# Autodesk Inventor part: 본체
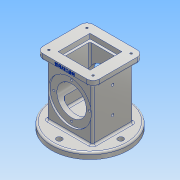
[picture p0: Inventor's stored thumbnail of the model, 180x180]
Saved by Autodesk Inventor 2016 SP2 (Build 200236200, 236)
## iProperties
Created: 2018-10
Part Number: 본체
Material: 알루미늄 6061
Document SubType Name: Modeling
Designer: Administrator
Mass: 984.858 g
Surface Area: 745.107 cm^2
Volume: 364.762 cm^3
Density: 2.7 g/cm^3
Appearance: 알루미늄 - 평지
Author: Administrator
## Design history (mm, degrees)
sketch "스케치1"
  geometry: C1 r 62.5 at (0, 0); 1 further point
  constraints: 1 centre point, 1 coincident
  dimensions: "d0" = 125 diameter of C1
extrude "돌출1" new body sketch "스케치1" distance "d1" = 10; taper "d2" = 0 deg
fillet "모깎기1" dims "d3" = 3
sketch "스케치2"
  geometry: C1 r 59.5 at (0, 0) reference; C2 r 4.5 at (0, 50); C3 r 4.5 at (-50, 0); C4 r 4.5 at (50, 0); C5 r 4.5 at (0, -50); A1 r 50 centre (0, 0) between (0, 50) and (-50, 0)
  constraints: 5 centre point, 4 point on circle, 1 coincident
  dimensions: "d4" = 100 diameter of A1; "d5" = 9 diameter of C3; "d6" = 9 diameter of C2; "d7" = 9 diameter of C5; "d8" = 9 diameter of C4
extrude "돌출2" cut sketch "스케치2" distance "d9" = 10; taper "d10" = 0 deg
sketch "스케치3"
  geometry: L1 (-37, -33)-(37, -33); L2 (37, -33)-(37, 33); L3 (37, 33)-(-37, 33); L4 (-37, 33)-(-37, -33); L5 (-37, -33)-(37, 33); L6 (37, -33)-(-37, 33); C1 r 59.5 at (0, 0) reference
  constraints: 12 end point, 2 midpoint, 2 parallel, 1 horizontal, 1 perpendicular
  dimensions: "d11" = 74 distance of L2.end L3.end; "d12" = 66 distance of L1.end L2.end
extrude "돌출3" join sketch "스케치3" distance "d13" = 88; taper "d14" = 0 deg
sketch "스케치4"
  geometry: L1 (-46, -41)-(46, -41); L2 (46, -41)-(46, 41); L3 (46, 41)-(-46, 41); L4 (-46, 41)-(-46, -41); L5 (-46, -41)-(46, 41); L6 (46, -41)-(-46, 41); 1 further point
  constraints: 12 end point, 2 midpoint, 2 parallel, 1 horizontal, 1 perpendicular
  dimensions: "d15" = 92 distance of L2.end L3.end; "d16" = 82 distance of L1.end L2.end
extrude "돌출4" join sketch "스케치4" distance "d17" = 10; taper "d18" = 0 deg
fillet "모깎기2" dims "d19" = 10
sketch "스케치5"
  geometry: A1 r 10 centre (-36, 31) between (-36, 41) and (-46, 31) reference; A2 r 10 centre (-36, -31) between (-46, -31) and (-36, -41) reference; A3 r 10 centre (36, -31) between (36, -41) and (46, -31) reference; A4 r 10 centre (36, 31) between (46, 31) and (36, 41) reference; 1 further point
hole "구멍1" sketch "스케치5" at (-36, 31), (36, 31), (36, -31), (-36, -31) diameter "d20" = 3.242; stored, may be unused: countersink angle "d24" = 90 deg, drill point angle "d26" = 118 deg; dims "d21" = 4, "d22" = 4, "d23" = 2, "d25" = 6
sketch "스케치6"
  geometry: L1 (37, -10)-(37, 44); C1 r 35 at (37, 44)
  constraints: 2 end point, 1 centre point, 1 coincident, 1 vertical
  dimensions: "d27" = 54 distance of L1.start L1.end; "d28" = 70 diameter of C1
extrude "돌출5" cut sketch "스케치6" distance "d29" = 3; taper "d30" = 0 deg
sketch "스케치7"
  geometry: C1 r 35 at (0, 0) reference; C2 r 24 at (0, 0); 1 further point
  constraints: 1 centre point, 1 coincident
  dimensions: "d31" = 48 diameter of C2
extrude "돌출6" cut sketch "스케치7" distance "d32" = 8; taper "d33" = 0 deg
sketch "스케치8" dims "d34" = 58
  geometry: C1 r 35 at (0, 0) reference; 3 further points
  constraints: 1 coincident, 1 vertical alignment, 2 other
hole "구멍2" sketch "스케치8" at (0, 29) diameter "d35" = 3.242; stored, may be unused: countersink angle "d39" = 90 deg, drill point angle "d41" = 118 deg; dims "d36" = 4, "d37" = 4, "d38" = 2, "d40" = 6
fillet "모깎기3" dims "d45" = 3
fillet "모깎기4" dims "d46" = 3
fillet "모깎기5" dims "d47" = 3
fillet "모깎기6" dims "d48" = 3
sketch "스케치9"
  geometry: L1 (-26, -26)-(26, -26); L2 (26, -26)-(26, 26); L3 (26, 26)-(-26, 26); L4 (-26, 26)-(-26, -26); L5 (-26, -26)-(26, 26); L6 (26, -26)-(-26, 26); 1 further point
  constraints: 12 end point, 2 midpoint, 2 parallel, 1 horizontal, 1 perpendicular
  dimensions: "d49" = 52 distance of L2.end L3.end; "d50" = 52 distance of L1.end L2.end
extrude "돌출7" cut sketch "스케치9" distance "d51" = 8; taper "d52" = 0 deg
sketch "스케치10"
  geometry: L1 (-22, -22)-(22, -22); L2 (22, -22)-(22, 22); L3 (22, 22)-(-22, 22); L4 (-22, 22)-(-22, -22); L5 (-22, -22)-(22, 22); L6 (22, -22)-(-22, 22); 1 further point
  constraints: 12 end point, 2 midpoint, 2 parallel, 1 horizontal, 1 perpendicular
  dimensions: "d53" = 44 distance of L2.end L3.end; "d54" = 44 distance of L1.end L2.end
extrude "돌출8" cut sketch "스케치10" distance "d55" = 74; taper "d56" = 0 deg
sketch "스케치11"
  geometry: C1 r 24 at (0, 0); A1 r 24 centre (0, 0) between (22, -9.592) and (22, 9.592) reference; 1 further point
  constraints: 1 centre point, 1 coincident
extrude "돌출9" cut sketch "스케치11" distance "d57" = 74; taper "d58" = 0 deg
sketch "스케치13"
  geometry: L1 (0, 0)-(-28, 0); L2 (-62.5, 0)-(62.5, 0) reference; L3 (-28, 0)-(-24.826, 18); L4 (-24.826, 18)-(0, 18); L5 (30, 13)-(-30, 13) reference; L6 (0, 18)-(0, 0)
  constraints: 8 end point, 1 parallel, 1 perpendicular, 1 point on line
  dimensions: "d59" = 28 distance of L1.start L1.end; "d60" = 80 deg angle of L1 L3; "d61" = 18 distance between parallel lines of L1 L4
revolve "회전1" sketch "스케치13" stored, may be unused: angle "d62" = 90 deg
fillet "모깎기7" dims "d63" = 3
fillet "모깎기8" dims "d64" = 3
fillet "모깎기9" dims "d65" = 3
sketch "스케치14"
  geometry: L1 (95, 30)-(58, 30); L2 (50.592, 49)-(50.592, 11) reference; L3 (58, 30)-(15, 30)
  constraints: 4 end point, 1 horizontal, 1 perpendicular
  dimensions: "d66" = 37 distance of L1.start L1.end; "d68" = 43 distance of L1.end L3.end
hole "구멍3" sketch "스케치14" at (15, 30), (58, 30) diameter "d69" = 4.134; stored, may be unused: countersink angle "d73" = 90 deg, drill point angle "d75" = 118 deg; dims "d70" = 20, "d71" = 4, "d72" = 2, "d74" = 21
node "작업 평면1"
sketch "스케치15"
  geometry: L1 (72, 0)-(82, 0) reference; L2 (-10, 0)-(-10, -7) reference; 2 further points
  constraints: 1 other
  dimensions: "d77" = 4 distance from line of L1 point (36, -4); "d78" = 46 distance from line of L2 point (36, -4)
feature "엠보싱1" sketch "스케치15" dims "d79" = 0.5, "d80" = 0
node "솔리드1"
mirror "대칭1"
pattern_circular "원형 패턴1" dims angle "d43" = 360 deg
mirror "대칭2"
other parameters: "d76" = 12.5
